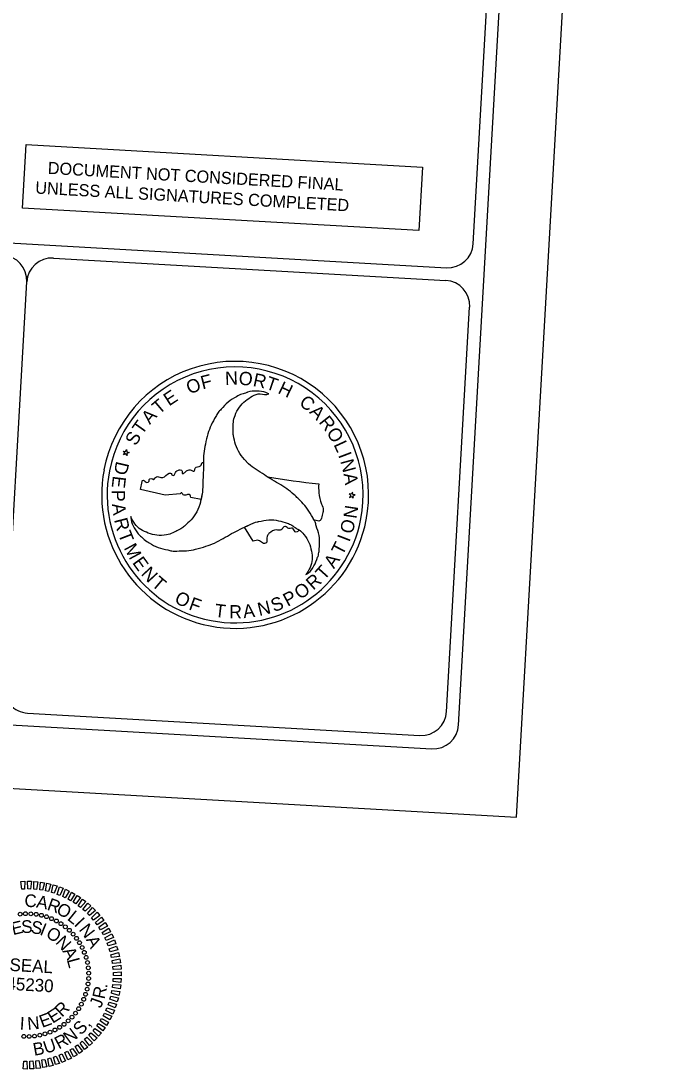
# Model space of a CAD drawing. Extents: x 2601627 to 2606907, y 616646 to 620530.
# Drawn here: x 2606132 to 2606907, y 616646 to 617888 of the extents above; entities that cross this region are included whole.
import ezdxf

# ---------------------------------------------------------------- set-up
doc = ezdxf.new("R2010")
doc.units = 0
for name, color, linetype in [('Sheet PE Seal Cell', 7, 'Continuous'), ('Sheet Sticker Exception Certification CELL', 7, 'Continuous'), ('Sheet Title CELL', 7, 'Continuous'), ('Stewart Plot Border Xerox6279 and LJ5000', 7, 'Continuous')]:
    doc.layers.add(name, color=color, linetype=linetype)

msp = doc.modelspace()

# ---------------------------------------------------------------- linework, layer by layer
at = {"layer": 'Sheet PE Seal Cell'}
msp.add_line((2606139.1, 616757.8), (2606139.1, 616757.8), dxfattribs=at)
for points in [[(2606132.5, 616859.6), (2606131.3, 616868.8), (2606136.2, 616869), (2606135.9, 616859.7)], [(2606139.6, 616859.8), (2606139.1, 616869.1), (2606143.9, 616868.9), (2606143, 616859.7)], [(2606146.7, 616859.5), (2606146.8, 616868.8), (2606151.7, 616868.3), (2606150.1, 616859.2)], [(2606153.8, 616858.7), (2606154.6, 616868), (2606159.3, 616867.2), (2606157.2, 616858.2)], [(2606160.8, 616857.4), (2606162.2, 616866.7), (2606166.9, 616865.5), (2606164.1, 616856.7)], [(2606167.7, 616855.7), (2606169.8, 616864.8), (2606174.4, 616863.3), (2606170.9, 616854.7)], [(2606174.4, 616853.4), (2606177.1, 616862.4), (2606181.6, 616860.6), (2606177.6, 616852.2)], [(2606181, 616850.7), (2606184.4, 616859.5), (2606188.7, 616857.3), (2606184.1, 616849.3)], [(2606187.4, 616847.6), (2606191.3, 616856.1), (2606195.5, 616853.6), (2606190.4, 616845.9)], [(2606193.5, 616844), (2606198.1, 616852.2), (2606202.1, 616849.5), (2606196.4, 616842.1)], [(2606199.4, 616840), (2606204.5, 616847.8), (2606208.3, 616844.8), (2606202.2, 616837.9)], [(2606205, 616835.6), (2606210.6, 616843.1), (2606214.2, 616839.8), (2606207.6, 616833.3)], [(2606210.3, 616830.8), (2606216.4, 616837.9), (2606219.8, 616834.3), (2606212.7, 616828.4)], [(2606215.2, 616825.6), (2606221.8, 616832.3), (2606224.9, 616828.5), (2606217.4, 616823)], [(2606219.7, 616820.2), (2606226.8, 616826.3), (2606229.6, 616822.4), (2606221.8, 616817.4)], [(2606223.9, 616814.4), (2606231.4, 616820), (2606233.9, 616815.9), (2606225.8, 616811.5)], [(2606227.6, 616808.3), (2606235.5, 616813.4), (2606237.7, 616809.1), (2606229.3, 616805.3)], [(2606230.9, 616802), (2606239.1, 616806.6), (2606241.1, 616802.1), (2606232.4, 616798.9)], [(2606233.8, 616795.5), (2606242.3, 616799.5), (2606243.9, 616794.9), (2606235, 616792.3)], [(2606236.2, 616788.8), (2606244.9, 616792.2), (2606246.2, 616787.5), (2606237.2, 616785.5)], [(2606238.1, 616781.9), (2606247.1, 616784.7), (2606248.1, 616779.9), (2606238.9, 616778.6)], [(2606239.6, 616775), (2606248.7, 616777.1), (2606249.3, 616772.3), (2606240.1, 616771.6)], [(2606240.5, 616767.9), (2606249.8, 616769.4), (2606250.1, 616764.6), (2606240.8, 616764.5)], [(2606241, 616760.8), (2606250.3, 616761.7), (2606250.3, 616756.8), (2606241, 616757.4)], [(2606240.4, 616746.6), (2606249.8, 616746.1), (2606249.1, 616741.3), (2606240, 616743.2)], [(2606240.9, 616753.7), (2606250.3, 616753.9), (2606249.9, 616749), (2606240.8, 616750.3)], [(2606237.9, 616732.6), (2606247.1, 616730.8), (2606245.7, 616726.2), (2606237, 616729.3)], [(2606239.4, 616739.6), (2606248.7, 616738.4), (2606247.6, 616733.7), (2606238.7, 616736.2)], [(2606233.4, 616719.1), (2606242.3, 616716.1), (2606240.3, 616711.6), (2606232.1, 616715.9)], [(2606235.9, 616725.8), (2606244.9, 616723.4), (2606243.2, 616718.8), (2606234.8, 616722.5)], [(2606227.1, 616706.3), (2606235.4, 616702.1), (2606232.9, 616698), (2606225.3, 616703.4)], [(2606230.5, 616712.6), (2606239.1, 616709), (2606236.8, 616704.7), (2606228.9, 616709.6)], [(2606219.1, 616694.6), (2606226.8, 616689.2), (2606223.6, 616685.5), (2606216.9, 616691.9)], [(2606223.3, 616700.3), (2606231.3, 616695.5), (2606228.5, 616691.6), (2606221.3, 616697.5)], [(2606209.5, 616684.1), (2606216.4, 616677.7), (2606212.7, 616674.5), (2606207, 616681.7)], [(2606214.5, 616689.2), (2606221.8, 616683.3), (2606218.4, 616679.8), (2606212.1, 616686.7)], [(2606192.6, 616671), (2606198, 616663.4), (2606193.8, 616661), (2606189.7, 616669.3)], [(2606198.6, 616675), (2606204.5, 616667.7), (2606200.4, 616665), (2606195.8, 616673)], [(2606204.2, 616679.3), (2606210.6, 616672.5), (2606206.7, 616669.5), (2606201.5, 616677.2)], [(2606138.5, 616655.8), (2606139, 616646.5), (2606134.2, 616646.7), (2606135.1, 616655.9)], [(2606145.6, 616656), (2606146.8, 616646.7), (2606141.9, 616646.6), (2606142.2, 616655.8)], [(2606152.7, 616656.7), (2606154.5, 616647.6), (2606149.7, 616647.1), (2606149.3, 616656.3)], [(2606159.7, 616657.9), (2606162.2, 616648.9), (2606157.4, 616648.1), (2606156.4, 616657.3)], [(2606166.6, 616659.6), (2606169.7, 616650.8), (2606165, 616649.6), (2606163.3, 616658.7)], [(2606173.4, 616661.8), (2606177.1, 616653.2), (2606172.5, 616651.7), (2606170.2, 616660.7)], [(2606180, 616664.4), (2606184.3, 616656.1), (2606179.8, 616654.3), (2606176.9, 616663.1)], [(2606186.5, 616667.5), (2606191.3, 616659.5), (2606186.9, 616657.4), (2606183.4, 616665.9)]]:
    msp.add_lwpolyline(points, close=True, dxfattribs=at)
for centre in [(2606130.5, 616830), (2606136.8, 616830.5), (2606143.2, 616830.4), (2606149.5, 616829.8), (2606155.7, 616828.6), (2606161.8, 616826.9), (2606167.8, 616824.6), (2606173.5, 616821.9), (2606178.9, 616818.6), (2606184.1, 616814.9), (2606188.9, 616810.8), (2606193.3, 616806.2), (2606197.3, 616801.3), (2606200.9, 616796.1), (2606204, 616790.5), (2606206.6, 616784.7), (2606208.7, 616778.7), (2606210.3, 616772.6), (2606211.3, 616766.3), (2606211.7, 616753.7), (2606211.8, 616760), (2606209.9, 616741.1), (2606211, 616747.3), (2606205.9, 616729.1), (2606208.1, 616735), (2606199.9, 616717.9), (2606203.1, 616723.3), (2606187.5, 616703.5), (2606192, 616707.9), (2606196.2, 616712.7), (2606166, 616690.2), (2606171.8, 616692.8), (2606177.3, 616695.9), (2606182.6, 616699.5), (2606134.9, 616685.2), (2606141.3, 616685.1), (2606147.6, 616685.5), (2606153.9, 616686.6), (2606160, 616688.1)]:
    msp.add_circle(centre, 2.25, dxfattribs=at)
at = {"layer": 'Sheet Sticker Exception Certification CELL'}
for p, q in [((2606133.4, 617666.4), (2606137.6, 617741.5)), ((2606137.6, 617741.5), (2606607.3, 617714.7)), ((2606607.3, 617714.7), (2606603, 617639.6)), ((2606603, 617639.7), (2606133.4, 617666.4))]:
    msp.add_line(p, q, dxfattribs=at)
at = {"layer": 'Sheet Title CELL'}
for p, q in [((2602382.7, 617837.9), (2606635.8, 617595.6)), ((2606170, 617607.1), (2606634.9, 617580.7)), ((2606111.1, 617099.7), (2606138.3, 617578.9)), ((2606425.3, 617446.5), (2606425, 617446.3)), ((2606425.3, 617446.5), (2606425, 617446.3)), ((2606254.5, 617376.4), (2606252.6, 617378.4)), ((2606252.6, 617378.4), (2606255.3, 617377.9)), ((2606253.2, 617373.9), (2606254.5, 617376.4)), ((2606255.3, 617377.9), (2606256.5, 617380.2)), ((2606256.5, 617380.2), (2606257, 617377.5)), ((2606257, 617377.5), (2606259.7, 617377)), ((2606259.7, 617377), (2606257.1, 617375.8)), ((2606257.1, 617375.8), (2606257.5, 617373.1)), ((2606255.6, 617375.1), (2606253.2, 617373.9)), ((2606257.5, 617373.1), (2606255.6, 617375.1)), ((2606273, 617333), (2606275.1, 617342.3)), ((2606423.7, 617348), (2606423.7, 617348)), ((2606302.3, 617326.2), (2606273, 617333)), ((2606320.1, 617328), (2606302.3, 617326.2)), ((2606523.1, 617327.5), (2606520.4, 617328)), ((2606520.4, 617328), (2606522.3, 617326)), ((2606522.3, 617326), (2606521, 617323.6)), ((2606524.4, 617329.8), (2606523.1, 617327.5)), ((2606524.8, 617327.2), (2606524.4, 617329.8)), ((2606527.5, 617326.8), (2606524.8, 617327.2)), ((2606525, 617325.5), (2606527.5, 617326.8)), ((2606345, 617321.1), (2606332.7, 617323.6)), ((2606521, 617323.6), (2606523.4, 617324.8)), ((2606523.4, 617324.8), (2606525.3, 617322.8)), ((2606525.3, 617322.8), (2606525, 617325.5)), ((2606406.8, 617271.9), (2606396.5, 617288.5)), ((2606396.5, 617288.5), (2606396.5, 617288.5)), ((2606540.6, 617296.9), (2606540.6, 617296.9))]:
    msp.add_line(p, q, dxfattribs=at)
for points in [[(2606650, 617053.9), (2606825.7, 620138.9)], [(2606667.4, 617623.8), (2606809.9, 620124.8)], [(2606635.9, 617069.8), (2606663.2, 617549)], [(2602185.5, 617278.1), (2606618.4, 617025.7)], [(2606139.3, 617068), (2606604.2, 617041.5)]]:
    msp.add_lwpolyline(points, dxfattribs=at)
for centre, radius, start, end in [((2606637.5, 617625.7), 30, 266.7403, 356.7403), ((2606108.4, 617580.6), 30, 356.7403, 86.7403), ((2606168.3, 617577.2), 30, 86.7403, 176.7403), ((2606633.3, 617550.8), 30, 356.7403, 86.7403), ((2606385.3, 617326.6), 158.2, 349.1609, 169.1609), ((2606385.3, 617326.6), 151.6, 349.1609, 169.1609), ((2606564.5, 618169.8), 833.8, 254.8394, 254.939), ((2606385.3, 617326.6), 158.1, 169.1609, 349.1609), ((2606385.3, 617326.6), 151.6, 169.1609, 349.1609), ((2606564.5, 618169.8), 833.8, 260.2784, 264.4845), ((2606141, 617098.1), 30, 176.7403, 266.7403), ((2606606, 617071.6), 30, 266.7403, 356.7403), ((2606620.1, 617055.8), 30, 266.7403, 356.7403)]:
    msp.add_arc(centre, radius, start, end, dxfattribs=at)
for points in [[(2606425, 617446.3), (2606421.6, 617447.9), (2606411.3, 617449.4), (2606400.1, 617448.1), (2606399.1, 617447.7), (2606393.3, 617446), (2606387, 617442.9), (2606377, 617436.6), (2606368.7, 617428), (2606365.3, 617424.3), (2606362.4, 617419.5), (2606356.9, 617409.2), (2606353.1, 617399), (2606350, 617386.7), (2606348.1, 617375.8), (2606347.8, 617364.4), (2606347.6, 617352.8), (2606347.1, 617341.6), (2606346.5, 617330.2), (2606344.4, 617319), (2606344.2, 617318.1), (2606339.9, 617306.6), (2606333.1, 617297.2), (2606325.3, 617289.7), (2606320.9, 617286.4), (2606314.9, 617283.3), (2606311.5, 617281.5), (2606303.8, 617279.3), (2606292.7, 617278.8), (2606282.4, 617281.4), (2606273.6, 617285.5), (2606266.5, 617292.3), (2606261.6, 617301)], [(2606469.2, 617232.1), (2606472.1, 617234.2), (2606478.7, 617242.4), (2606483.1, 617252.7), (2606483.5, 617253.8), (2606484.7, 617259.7), (2606485.2, 617266.8), (2606484.8, 617278.6), (2606481.4, 617290), (2606480, 617294.8), (2606477.2, 617299.8), (2606471.1, 617309.7), (2606464.2, 617318.1), (2606455.1, 617326.8), (2606446.5, 617333.9), (2606436.8, 617340), (2606426.9, 617345.9), (2606417.6, 617351.9), (2606407.8, 617358.2), (2606399.3, 617365.5), (2606398.6, 617366.3), (2606390.7, 617375.7), (2606385.9, 617386.3), (2606383.3, 617396.8), (2606382.8, 617402.2), (2606383.1, 617408.9), (2606383.2, 617412.9), (2606385.2, 617420.6), (2606390.4, 617430.5), (2606397.7, 617438), (2606405.6, 617443.5), (2606415.1, 617446.3), (2606425, 617446.3), (2606425.3, 617446.5)], [(2606275.1, 617342.3), (2606275, 617343.2), (2606276.8, 617343.9), (2606280.8, 617341.3), (2606283.4, 617342.8), (2606283.6, 617344.7), (2606285.7, 617346.2), (2606288.6, 617345), (2606292, 617348), (2606294.6, 617348.1), (2606299.8, 617347.1), (2606307.3, 617352.2), (2606309.9, 617352), (2606310.3, 617350.3), (2606311.8, 617349.6), (2606315.5, 617354.3), (2606316.3, 617354.9), (2606321.6, 617355.9), (2606322.7, 617354.7), (2606322.6, 617352.3), (2606323.2, 617351.7), (2606325, 617352.6), (2606327.7, 617354.9), (2606332.1, 617356.2), (2606336.6, 617354.8), (2606338.1, 617358.4), (2606344.1, 617361), (2606345.6, 617362.9), (2606346.3, 617365.1)], [(2606347.8, 617364.6), (2606347.8, 617364.4), (2606347.6, 617352.8), (2606347.1, 617341.6), (2606346.5, 617330.2), (2606345, 617321.1)], [(2606479.2, 617296.7), (2606477.2, 617299.8), (2606471.1, 617309.7), (2606464.2, 617318.1), (2606455.1, 617326.8), (2606446.5, 617333.9), (2606436.8, 617340), (2606426.9, 617345.9), (2606423.7, 617348)], [(2606484.3, 617339.8), (2606484.5, 617329.1), (2606487.6, 617315.8), (2606489.8, 617308.5), (2606488.6, 617302.7), (2606486, 617296.1), (2606479.2, 617296.7)], [(2606332.7, 617323.6), (2606332, 617326.1), (2606329.7, 617327.2), (2606326.2, 617326.1), (2606323.8, 617326.7), (2606321.5, 617329.2), (2606320.1, 617328)], [(2606261.6, 617301), (2606262, 617297.3), (2606265.8, 617287.5), (2606272.5, 617278.5), (2606273.3, 617277.8), (2606277.7, 617273.6), (2606283.6, 617269.7), (2606294.1, 617264.2), (2606305.6, 617261.4), (2606310.5, 617260.2), (2606316.3, 617260.1), (2606327.7, 617260.5), (2606338.5, 617262.2), (2606350.7, 617265.8), (2606361, 617269.6), (2606371.2, 617275), (2606381.2, 617280.7), (2606391.2, 617285.8), (2606401.5, 617290.9), (2606412.1, 617294.8), (2606413.2, 617295), (2606425.3, 617297.1), (2606436.7, 617295.9), (2606447, 617293), (2606452.3, 617290.8), (2606457.7, 617287), (2606461.2, 617285.1), (2606466.9, 617279.5), (2606472.8, 617270.1), (2606475.7, 617260), (2606476.5, 617250.2), (2606474.2, 617240.7), (2606469.2, 617232.1)], [(2606396.5, 617288.5), (2606401.5, 617290.9), (2606412.1, 617294.8), (2606413.2, 617295), (2606425.3, 617297.1), (2606436.7, 617295.9), (2606447, 617293), (2606452.3, 617290.8), (2606457.7, 617287), (2606460.9, 617285.2)], [(2606460.9, 617285.1), (2606458.9, 617282.7), (2606456.6, 617283), (2606453.1, 617287), (2606447.9, 617287), (2606445.8, 617288.7), (2606444.3, 617289.1), (2606439.8, 617285.2), (2606434.6, 617285.1), (2606425.4, 617280.7), (2606423.1, 617277.5), (2606422.3, 617270), (2606420, 617268.9), (2606417.7, 617269.7), (2606413.1, 617272.6), (2606406.8, 617271.9)]]:
    msp.add_spline(points, degree=3, dxfattribs=at)
at = {"layer": 'Stewart Plot Border Xerox6279 and LJ5000'}
msp.add_lwpolyline([(2601627.1, 617234.9), (2606718.9, 616944.8), (2606906.6, 620239.5), (2601814.8, 620529.5)], close=True, dxfattribs=at)

# ---------------------------------------------------------------- texts
at = {"layer": 'Sheet PE Seal Cell'}
for s, rotation, p in [('C', 358.7021, (2606135.6, 616838.5)), ('A', 349.197, (2606149, 616838)), ('R', 340.1496, (2606161.5, 616835.4)), ('O', 331.9409, (2606172.3, 616831.4)), ('L', 321.2157, (2606185.5, 616823.9)), ('E', 13.7262, (2606122.1, 616805)), ('S', 1.964, (2606132.1, 616807.5)), ('S', 350.005, (2606142.5, 616807.8)), ('I', 338.0461, (2606152.8, 616806)), ('I', 313.7506, (2606193.7, 616817.3)), ('N', 307.8106, (2606199.5, 616811.4)), ('O', 329.2906, (2606160, 616803.4)), ('N', 313.4818, (2606171.6, 616795.9)), ('A', 297.6002, (2606208.1, 616799.8)), ('A', 298.4318, (2606180.4, 616786.2)), ('SEAL', 356.7403, (2606117.7, 616762.8)), ('L', 285.0959, (2606185.8, 616775.9)), ('045230', 356.7403, (2606102.9, 616741.1)), ('R', 77.6307, (2606230.5, 616728.6)), ('.', 85.8394, (2606233.8, 616741.9)), ('J', 70.7928, (2606226.4, 616717.9)), ('E', 32.021, (2606169, 616700)), ('R', 43.7832, (2606180.1, 616707.3)), ('I', 356.4532, (2606129.8, 616693.4)), ('N', 5.2087, (2606139.7, 616692.7)), ('E', 20.2587, (2606156.6, 616695.1)), ('N', 36.4998, (2606188.7, 616675.6)), ('S', 46.7102, (2606202.5, 616685.7)), (',', 54.8235, (2606212.1, 616695.4)), ('U', 18.5669, (2606161, 616664.3)), ('R', 28.2911, (2606176.5, 616669.4)), ('B', 10.2247, (2606147.2, 616662.1))]:
    msp.add_text(s, height=15, rotation=rotation, dxfattribs=at).set_placement(p)
at = {"layer": 'Sheet Sticker Exception Certification CELL'}
for s, p in [('DOCUMENT NOT CONSIDERED FINAL', (2606163, 617706.9)), ('UNLESS ALL SIGNATURES COMPLETED', (2606148.2, 617683.6))]:
    msp.add_text(s, height=14.4, rotation=356.7398, dxfattribs=at).set_placement(p)
at = {"layer": 'Sheet Title CELL'}
for s, height, rotation, p in [('O', 15.8, 21.3785, (2606331.1, 617445.5)), ('F', 15.8, 14.2316, (2606346.7, 617451.5)), ('N', 15.8, 2.1447, (2606373.6, 617456.8)), ('O', 15.8, 354.6466, (2606389, 617457.3)), ('R', 15.8, 348.0366, (2606405.6, 617455.7)), ('T', 15.8, 341.387, (2606420.4, 617452.6)), ('E', 15.7, 33.3178, (2606307, 617431.3)), ('H', 15.7, 334.3023, (2606435, 617447.6)), ('T', 15.7, 40.4335, (2606295.2, 617421.3)), ('C', 15.7, 321.9599, (2606460.1, 617433.9)), ('A', 15.8, 47.4887, (2606284.2, 617409.3)), ('A', 15.8, 314.4629, (2606472.4, 617424.1)), ('T', 15.8, 54.541, (2606275.1, 617396.9)), ('R', 15.8, 308.099, (2606483.8, 617412.6)), ('S', 15.8, 60.9172, (2606267.8, 617383.8)), ('O', 15.8, 300.9794, (2606493, 617400.7)), ('L', 15.7, 294.7457, (2606501.7, 617386.3)), ('I', 15.8, 290.7563, (2606507.1, 617373.8)), ('D', 15.8, 257.0139, (2606244.6, 617367.2)), ('N', 15.8, 285.0562, (2606509.7, 617366.6)), ('A', 15.8, 277.6243, (2606513.7, 617351.6)), ('E', 15.7, 263.3018, (2606240.6, 617349.6)), ('P', 15.8, 270.8342, (2606239, 617332.5)), ('A', 15.7, 277.4268, (2606239.2, 617315.7)), ('N', 15.8, 81.369, (2606529.1, 617297.8)), ('R', 15.8, 284.4954, (2606241.8, 617297.2)), ('O', 15.7, 74.121, (2606524, 617279.4)), ('T', 15.8, 291.1459, (2606246.3, 617280.4)), ('I', 15.8, 68.9854, (2606520.5, 617270)), ('M', 15.7, 298.381, (2606253, 617263.8)), ('T', 15.7, 63.3355, (2606512.6, 617254)), ('E', 15.7, 305.8477, (2606262.9, 617246.3)), ('A', 15.8, 56.2511, (2606502.4, 617238.4)), ('N', 15.8, 312.8193, (2606273, 617232.6)), ('T', 15.7, 48.164, (2606490.7, 617224.8)), ('T', 15.7, 319.6613, (2606285.2, 617219.7)), ('R', 15.8, 42.0642, (2606477.9, 617213)), ('O', 15.8, 34.8751, (2606462.3, 617202)), ('O', 15.8, 332.965, (2606312.3, 617199.6)), ('F', 15.8, 340.1302, (2606329.4, 617191.2)), ('S', 15.7, 20.9913, (2606431.2, 617187.5)), ('P', 15.8, 28.1831, (2606447.5, 617193.9)), ('T', 15.7, 353.0394, (2606360.3, 617182.2)), ('R', 15.8, 359.996, (2606378.1, 617180.2)), ('A', 15.7, 6.7492, (2606395.5, 617180.5)), ('N', 15.7, 13.7808, (2606414, 617183))]:
    msp.add_text(s, height=height, rotation=rotation, dxfattribs=at).set_placement(p)

doc.saveas('drawing.dxf')
